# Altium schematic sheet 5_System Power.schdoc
size 309 x 223 mm; Symbol: Sheet-Symbol_A4; Device: Sheet-Symbol_A4; Company: EasyEDA.com; Drawed: EasyEDA Pro; Reviewed: EasyEDA Pro; Version: V0.1; Page Size: A4; @Project Name: CM4-Nvme-NAS-main; @Page Count: 6; @Update Date: 2023-05-19; @Create Date: 2023-04-27; @Schematic Name: RaspberryPiNVMeNAS; Part Number: JLCPCB-002; @Page No: 2; @Page Name: System Power
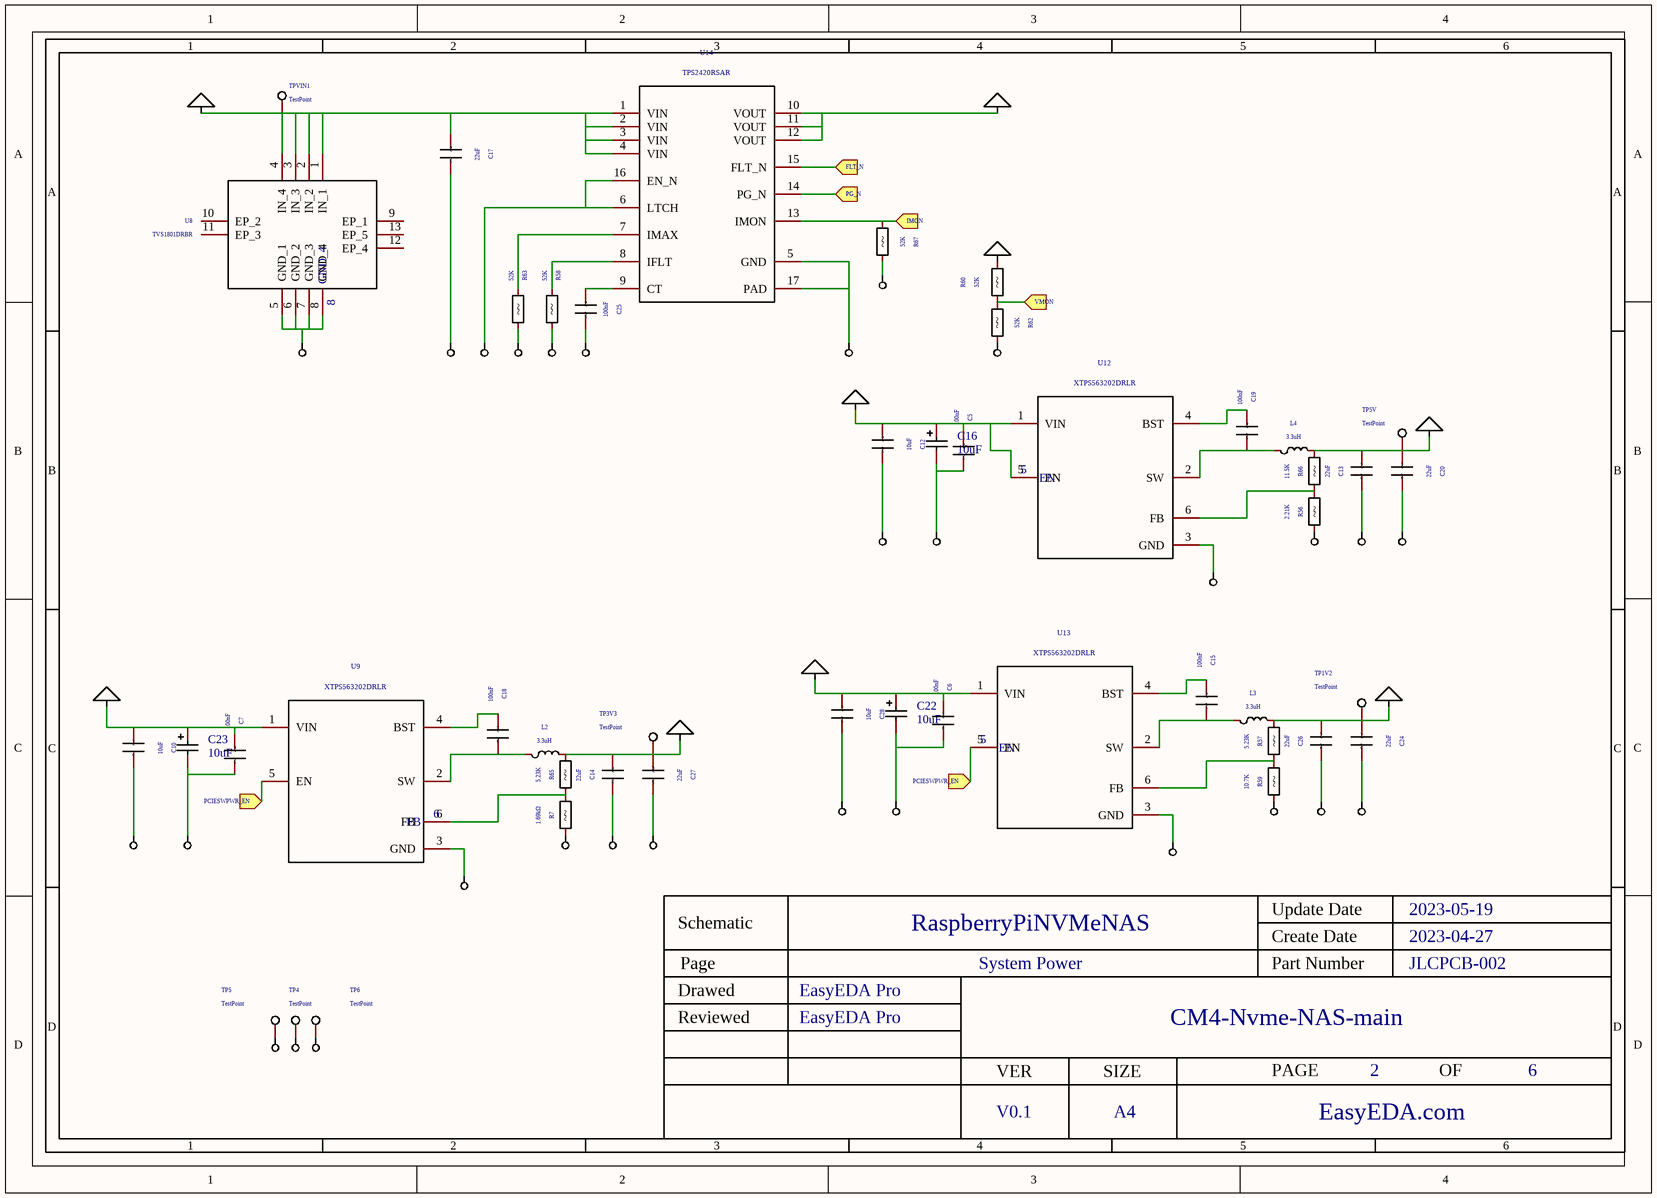
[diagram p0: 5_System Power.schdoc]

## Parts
C5  100nF  [C0402]
C6  100nF  [C0402]
C7  100nF  [C0402]
C10  10uF  [C0805]
C12  10uF  [C0805]
C13  22uF  [C0805]
C14  22uF  [C0805]
C15  100nF  [C0402]
C16  value 10uF  [CAP-SMD_L3.2-W1.6-RD-C7171]  (hidden comment: TAJA106K016RNJ)
C17  22uF  [C0805]
C18  100nF  [C0402]
C19  100nF  [C0402]
C20  22uF  [C0805]
C22  value 10uF  [CAP-SMD_L3.2-W1.6-RD-C7171]  (hidden comment: TAJA106K016RNJ)
C23  value 10uF  [CAP-SMD_L3.2-W1.6-RD-C7171]  (hidden comment: TAJA106K016RNJ)
C24  22uF  [C0805]
C25  100nF  [C0402]
C26  22uF  [C0805]
C27  22uF  [C0805]
C28  10uF  [C0805]
L2  value 3.3uH  [Inductor_SMD:L_Vishay_IHLP-1212]  (hidden comment: Device_L)
L3  value 3.3uH  [Inductor_SMD:L_Vishay_IHLP-1212]  (hidden comment: Device_L)
L4  value 3.3uH  [Inductor_SMD:L_Vishay_IHLP-1212]  (hidden comment: Device_L)
R7  1.69kΩ  [R0402]
R56  value 2.21K  [Resistor_SMD:R_0402_1005Metric]  (hidden comment: Device_R)
R57  value 5.23K  [Resistor_SMD:R_0402_1005Metric]  (hidden comment: Device_R)
R58  value 52K  [Resistor_SMD:R_0402_1005Metric]  (hidden comment: Device_R)
R59  value 10.7K  [Resistor_SMD:R_0402_1005Metric]  (hidden comment: Device_R)
R60  value 52K  [Resistor_SMD:R_0402_1005Metric]  (hidden comment: Device_R)
R62  value 52K  [Resistor_SMD:R_0402_1005Metric]  (hidden comment: Device_R)
R63  value 52K  [Resistor_SMD:R_0402_1005Metric]  (hidden comment: Device_R)
R65  value 5.23K  [Resistor_SMD:R_0402_1005Metric]  (hidden comment: Device_R)
R66  value 11.5K  [Resistor_SMD:R_0402_1005Metric]  (hidden comment: Device_R)
R67  value 52K  [Resistor_SMD:R_0402_1005Metric]  (hidden comment: Device_R)
TP1V2  value TestPoint  [TestPoint:TestPoint_Pad_D1.0mm]  (hidden comment: Connector_TestPoint)
TP3V3  value TestPoint  [TestPoint:TestPoint_Pad_D1.0mm]  (hidden comment: Connector_TestPoint)
TP4  value TestPoint  [TestPoint:TestPoint_Pad_D1.0mm]  (hidden comment: Connector_TestPoint)
TP5  value TestPoint  [TestPoint:TestPoint_Pad_D1.0mm]  (hidden comment: Connector_TestPoint)
TP5V  value TestPoint  [TestPoint:TestPoint_Pad_D1.0mm]  (hidden comment: Connector_TestPoint)
TP6  value TestPoint  [TestPoint:TestPoint_Pad_D1.0mm]  (hidden comment: Connector_TestPoint)
TPVIN1  value TestPoint  [TestPoint:TestPoint_Pad_D1.0mm]  (hidden comment: Connector_TestPoint)
U8  value TVS1801DRBR  NUMBER: 8  NAME: GND_4  [footprint:TPS73601DRBR]  (hidden comment: TVS1801DRBR_TVS1801DRBR)
U9  value XTPS563202DRLR  NAME: FB  NUMBER: 6  [SOT-563-6_L1.6-W1.2-P0.5-LS1.6-BR]  (hidden comment: TPS563202DRLR)
U12  value XTPS563202DRLR  NAME: EN  NUMBER: 5  [SOT-563-6_L1.6-W1.2-P0.5-LS1.6-BR]  (hidden comment: TPS563202DRLR)
U13  value XTPS563202DRLR  NAME: EN  NUMBER: 5  [SOT-563-6_L1.6-W1.2-P0.5-LS1.6-BR]  (hidden comment: TPS563202DRLR)
U14  value TPS2420RSAR  [SOT-563-6_L1.6-W1.2-P0.5-LS1.6-BR]  (hidden comment: TPS563202DRLR)

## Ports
FLT_N (in), IMON (in), PCIESWPWR_EN (in), PG_N (in), VMON (in)

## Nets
+1V2: C24.1 C26.1 L3.2 R57.1 TP1V2.1
+12V: C5.1 C6.1 C7.1 C10.1 C12.1 C16.1 C22.1 C23.1 C28.1 R60.2 U9.1(VIN) U12.1(VIN) U12.5(EN) U13.1(VIN)
GND: C5.2 C6.2 C7.2 C10.2 C12.2 C13.2 C16.2 C17.2 C20.2 C22.2 C23.2 C25.2 C28.2 R7.2 R56.2 R58.2 R59.2 R62.2 R63.2 R67.2 TP4.1 TP5.1 TP6.1 U8.5(GND_1) U8.6(GND_2) U8.7(GND_3) U8.8(GND_4) U9.3(GND) U14.5(GND) U14.6(LTCH) U14.16(EN_N) U14.17(PAD)
POWER_+3.3V: C14.1 C27.1 L2.2 R65.1 TP3V3.1
POWER_+5V: C13.1 C20.1 L4.2 R66.1 TP5V.1
POWER_+12P: C17.1 TPVIN1.1 U8.1(IN_1) U8.2(IN_2) U8.3(IN_3) U8.4(IN_4) U14.1(VIN) U14.2(VIN) U14.3(VIN) U14.4(VIN)
POWER_+12V: U14.10(VOUT) U14.11(VOUT) U14.12(VOUT)
POWER_GND: C14.2 C24.2 C26.2 C27.2 U12.3(GND) U13.3(GND)
FLT_N: U14.15(FLT_N) ; port FLT_N
IMON: R67.1 U14.13(IMON) ; port IMON
PCIESWPWR_EN: U9.5(EN) U13.5(EN) ; port PCIESWPWR_EN
PG_N: U14.14(PG_N) ; port PG_N
VMON: R60.1 R62.1 ; port VMON
NetC15_1: C15.1 U13.4(BST)
NetC15_2: C15.2 L3.1 U13.2(SW)
NetC18_1: C18.1 U9.4(BST)
NetC18_2: C18.2 L2.1 U9.2(SW)
NetC19_1: C19.1 U12.4(BST)
NetC19_2: C19.2 L4.1 U12.2(SW)
NetC25_1: C25.1 U14.9(CT)
NetR7_1: R7.1 R65.2 U9.6(FB)
NetR56_1: R56.1 R66.2 U12.6(FB)
NetR57_2: R57.2 R59.1 U13.6(FB)
NetR58_1: R58.1 U14.8(IFLT)
NetR63_1: R63.1 U14.7(IMAX)

Not connected (* = marked no-connect by the designer): U8 9(EP_1) 10(EP_2) 11(EP_3) 12(EP_4) 13(EP_5)

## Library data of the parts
C5-C7 C15 C18 C19 C25 = CL05B104KO5NNNC: Capacitance: Tolerance:±10% Tolerance:±10% Voltage Rated: Temperature Coefficient:; Manufacturer: SAMSUNG(三星); Add into BOM: yes; Tolerance: ±10%; Origin Footprint: C_0402_1005Metric
C10 C28 = CL21A106KAYNNNE_C15850: Capacitance: Tolerance:±10% Tolerance:±10% Voltage Rated: Temperature Coefficient:; Manufacturer: SAMSUNG(三星); Add into BOM: yes; Tolerance: ±10%; Origin Footprint: C_0805_2012Metric
C12 = CL21A106KAYNNNE_C15850: Capacitance: Tolerance:±10% Tolerance:±10% Voltage Rated: Temperature Coefficient:; Manufacturer: SAMSUNG(三星); Add into BOM: yes; Tolerance: ±10%; Origin Footprint: C_0805_2012Metric; Pin Type: IN
C13 C14 C20 C24 C26 C27 = GRM21BR60J226ME39L: Capacitance: Tolerance:±20% Tolerance:±20% Voltage Rated: Temperature Coefficient:; Manufacturer: muRata(村田); Add into BOM: yes; Tolerance: ±20%; Origin Footprint: C_0805_2012Metric
C16 C22 C23 = TAJA106K016RNJ: Capacitance: Tolerance:±10% Tolerance:±10% Rated Voltage: Equivalent Series Resistance(ESR):3Ω@100kHz Operating Temperature:-55℃~+125℃ Operating Temperature:-55℃~+125℃; Manufacturer: Kyocera AVX; Add into BOM: yes; Tolerance: ±10%; Origin Footprint: C_0805_2012Metric
C17 = GRM21BR60J226ME39L: Capacitance: Tolerance:±20% Tolerance:±20% Voltage Rated: Temperature Coefficient:; Manufacturer: muRata(村田); Add into BOM: yes; Tolerance: ±20%; Origin Footprint: C_0402_1005Metric
L2-L4 = Device_L: Add into BOM: yes; Origin Footprint: L_Vishay_IHLP-1212
R7 = CR0402FF1691G: Type:Thick Film Resistors Resistance: Tolerance:±1% Tolerance:±1% Power(Watts): Temperature Coefficient:±200ppm/℃ Temperature Coefficient:±200ppm/℃ Overload Voltage (Max): Operating Temperature Range:-55℃~+125℃ Operating Temperature Range:-55℃~+125℃; Manufacturer: LIZ(丽智电子); Add into BOM: yes; Tolerance: ±1%; Origin Footprint: R_0402_1005Metric; Pin Type: IN
R56-R60 R62 R63 R65-R67 = Device_R: Add into BOM: yes; Origin Footprint: R_0402_1005Metric
TP1V2 TP3V3 TP4 TP5 TP5V TP6 TPVIN1 = Connector_TestPoint: Add into BOM: yes; Origin Footprint: TestPoint_Pad_D1.0mm
U8 = TVS1801DRBR_TVS1801DRBR: 18-V bidirectional flat-clamp surge protection device; Manufacturer_Name: Texas Instruments; Add into BOM: yes; Origin Footprint: TPS73601DRBR; Pin Type: IN
U9 U12 U13 = TPS563202DRLR: Function:Step-down type Synchronous Rectification:Yes Output Type:Adjustable Number of Outputs:1 Topology:Step-down Input Voltage:4.3V~17V Input Voltage:4.3V~17V Output Voltage:0.806V~7V Output Voltage:0.806V~7V Output Current (Max):3A Switching Frequency; Manufacturer: TI(德州仪器); Add into BOM: yes; Number of Outputs: 1; Output Current (Max): 3A; Switching Frequency: 580kHz; Pin Type: IN
U14 = TPS563202DRLR: Function:Step-down type Synchronous Rectification:Yes Output Type:Adjustable Number of Outputs:1 Topology:Step-down Input Voltage:4.3V~17V Input Voltage:4.3V~17V Output Voltage:0.806V~7V Output Voltage:0.806V~7V Output Current (Max):3A Switching Frequency; Manufacturer: TI(德州仪器); Add into BOM: yes; Number of Outputs: 1; Output Current (Max): 3A; Switching Frequency: 580kHz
